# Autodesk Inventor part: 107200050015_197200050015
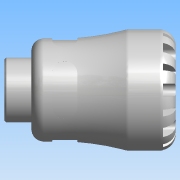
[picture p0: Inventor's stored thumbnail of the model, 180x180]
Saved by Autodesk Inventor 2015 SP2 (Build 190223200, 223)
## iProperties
Created: 2016-12
Part Number: 107200050015_197200050015
Material: PVC-Piping
Description: PLASSON MALE INTEGRAL BRASS THREAD 50X1.1/2" SERIES 1
Document SubType Name: Modeling
Designer: KIM
Mass: 61.7504 g
Surface Area: 140.097 cm^2
Volume: 44.1074 cm^3
Density: 1.4 g/cm^3
Appearance: Smooth - White
Author: KIM
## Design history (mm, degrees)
derived "1072.ipt"
feature "Solid1::1072.ipt"
tag "TaggingFeature1"
body "Solid1"
other parameters: "d1" = 34.02, "d3" = 62.5, "d4" = 85, "d6" = 81, "d8" = 72.25, "d13" = 9, "d14" = 9, "d15" = 0, "d17" = 360 deg, "d19" = 8 deg, "d20" = 1, "d21" = 1, "d22" = 8 deg, "d24" = 0, "d26" = 360 deg, "d32" = 8.5, "d33" = 8.5, "d34" = 45.485, "d38" = 19, "d39" = 1.36455, "d42" = 17.5, "d43" = 11.5, "d45" = 17.64, "d46" = 0, "d59" = 360 deg, "d61" = 14.875, "d62" = 1, "d64" = 0, "d65" = 0.85, "d68" = 7.14286, "E_" = 85, "l_" = 81, "R_" = 45.485, "l_2" = 19, "d9" = 11.25, "d11" = 85, "d12" = 62.5
